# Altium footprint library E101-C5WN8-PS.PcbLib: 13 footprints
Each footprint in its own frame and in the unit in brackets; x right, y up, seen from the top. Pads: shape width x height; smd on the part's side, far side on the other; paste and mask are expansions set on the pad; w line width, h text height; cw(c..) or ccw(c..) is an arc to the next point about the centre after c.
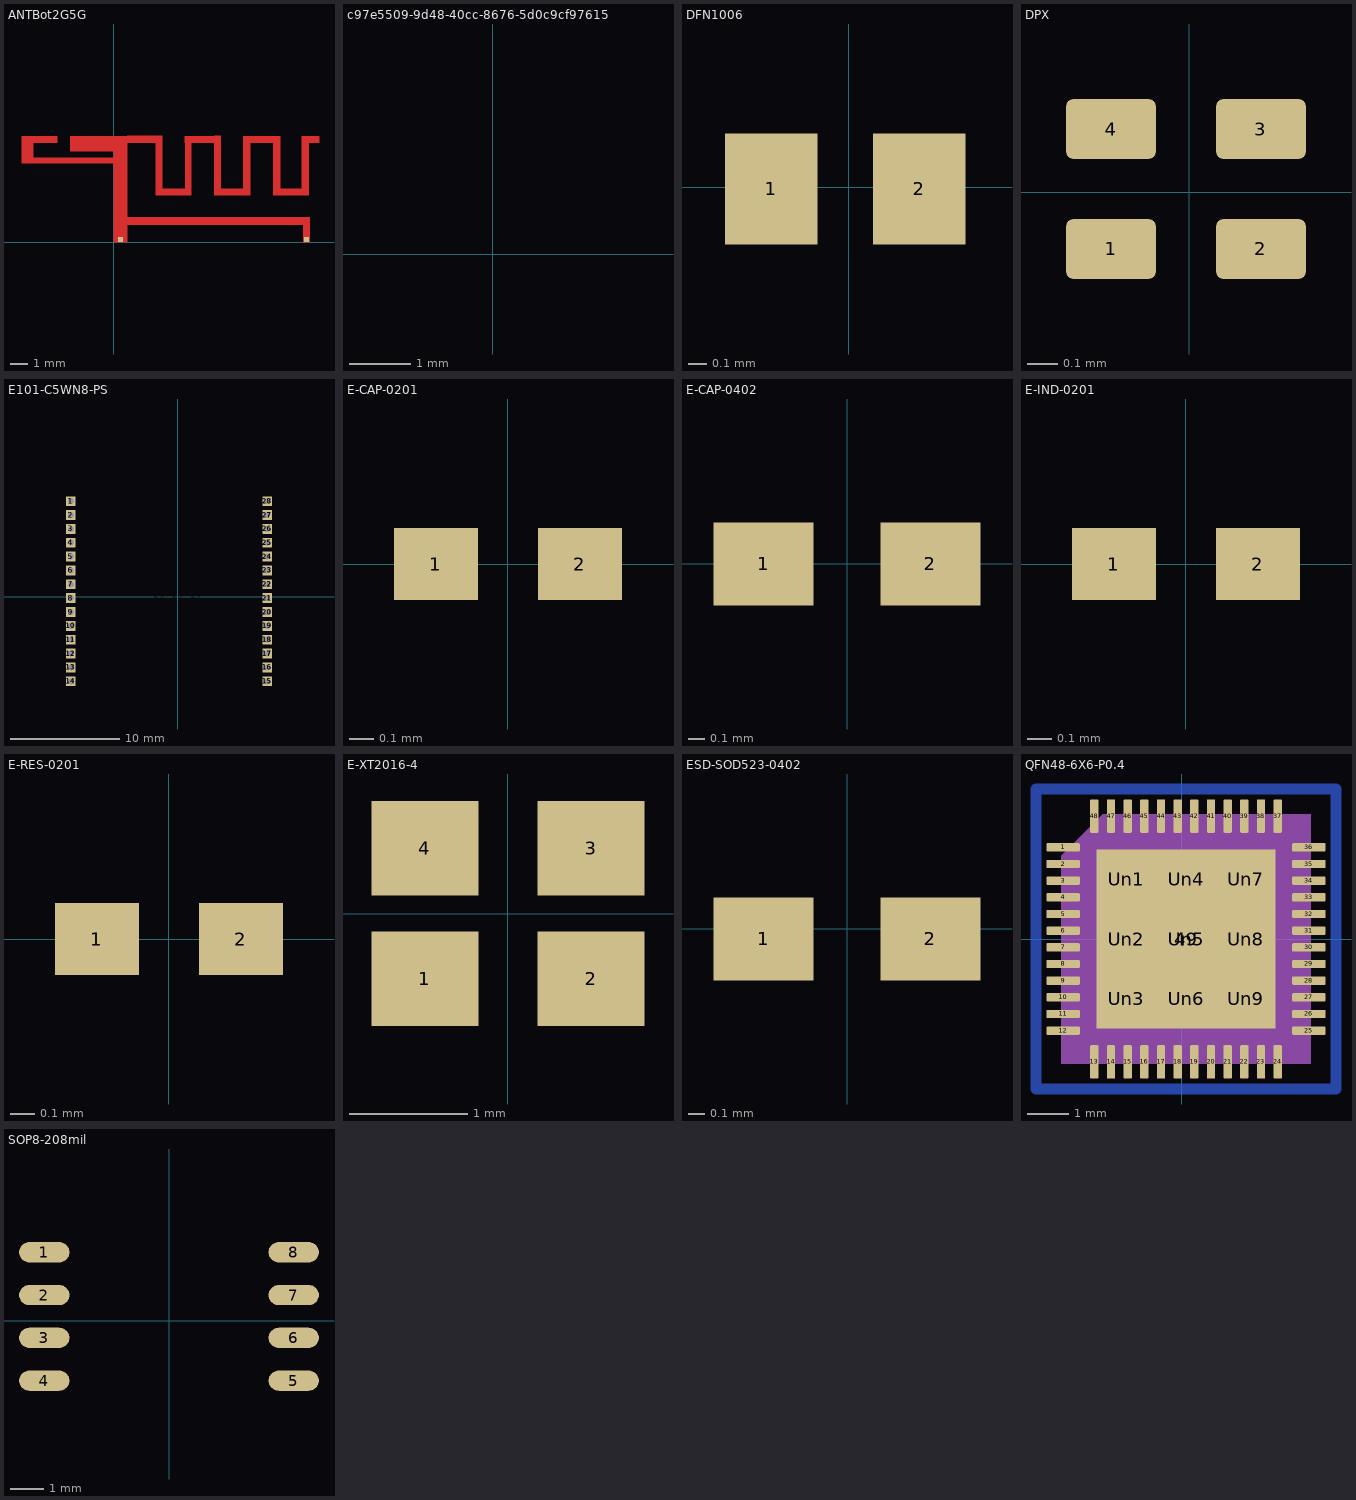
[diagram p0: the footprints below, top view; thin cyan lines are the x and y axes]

## ANTBot2G5G [mm]
pads (2):
  rect 0.3x0.3 smd paste-0.3 mask-0.3: 1(0.379,0.15) 2(11.046,0.15)
Top Layer:
  region: 4.43,3.06 4.43,2.683 4.427,2.68 2.78,2.68 2.78,3.07 4.42,3.07
  region: 11.239,0 10.855,0 10.855,0.987 0.765,0.987 0.765,1.43 11.239,1.43
  region: 6.14,5.7 4.07,5.7 4.07,6.08 4.08,6.09 6.14,6.09
  region: 2.783,2.683 2.78,2.68 2.39,2.68 2.39,5.7 2.783,5.7
  region: 4.43,3.06 4.42,3.05 4.08,3.05 4.08,6.09 4.43,6.09
  region: 7.43,2.68 6.14,2.68 6.13,2.69 6.13,3.07 7.43,3.07
  region: 6.14,6.09 6.14,2.68 5.75,2.68 5.75,6.1 6.13,6.1
  region: 2.783,5.7 0.765,5.7 0.765,6.093 2.783,6.093
  region: 11.77,5.7 11.18,5.7 11.18,6.09 11.77,6.09
  region: 9.54,5.7 7.43,5.7 7.43,6.09 9.54,6.09
  region: 0,5.22 -2.52,5.22 -2.52,6.09 0,6.09
  region: -3.25,5.7 -4.63,5.7 -4.63,6.09 -3.25,6.09
  region: 0,4.52 -5.29,4.52 -5.29,4.83 0,4.83
  region: -4.63,4.83 -5.29,4.83 -5.29,6.09 -4.63,6.09
  region: 10.79,2.68 9.54,2.68 9.54,3.07 10.79,3.07
  region: 11.18,2.68 10.79,2.68 10.79,6.09 11.18,6.09
  region: 9.54,2.68 9.14,2.68 9.14,6.09 9.54,6.09
  region: 7.83,2.68 7.43,2.68 7.43,6.09 7.83,6.09
  region: 0.77,0 0,0 0,6.09 0.77,6.09
Mid-Layer 2:
  region: -5.44,4.81 -4.7,4.81 -4.7,4.8 -5.44,4.8 -5.45,4.81 -5.45,4.82
  region: -1.91,5.22 -5.45,5.22 -5.45,6.09 -1.91,6.09
  region: 0.77,1.43 0,1.43 0,6.09 0.77,6.09

## c97e5509-9d48-40cc-8676-5d0c9cf97615 [mm]
Mid-Layer 7:
  lines w0.254: -2.019,-0.673 -2.007,-0.673 ; -2.007,-0.66 -1.981,-0.66 ; -2.007,-0.648 -1.956,-0.648 ; -1.981,-0.622 -1.918,-0.622 -1.803,-0.559 ; -0.381,0.305 -1.435,0.318 ; 0.025,-0.419 -0.838,-0.394 ; 0.089,-0.178 0.178,-0.178 ; 0.114,-0.191 0.191,-0.191 ; 0.127,-0.203 0.203,-0.203 ; 0.165,-0.165 -0.368,-0.114 ; 0.165,1.486 1.181,1.499 -0.064,1.511 1.168,1.524 -0.165,1.537 1.156,1.549 -0.241,1.562 1.143,1.575 -0.343,1.6 ; 0.33,1.473 1.207,1.473 0.47,1.46 1.219,1.448 0.635,1.435 1.232,1.422 0.737,1.41 1.245,1.397 0.8,1.384 1.257,1.372 0.864,1.359 1.27,1.283 0.978,1.27 1.207,1.257 1.029,1.206 1.118,1.206 ; 0.368,-0.508 0.445,-0.508 ; 0.368,-0.495 0.445,-0.495 ; 0.381,-0.533 0.457,-0.533 ; 0.381,-0.521 0.445,-0.521 ; 0.394,-0.559 0.457,-0.559 ; 0.394,-0.546 0.457,-0.546 ; 0.406,-0.584 0.47,-0.584 ; 0.419,-0.635 0.508,-0.635 ; 0.419,-0.622 0.495,-0.622 0.406,-0.61 0.483,-0.61 ; 0.495,0.191 0.597,0.216 ; 0.61,-0.406 0.711,-0.406 ; 0.61,0.064 0.699,0.064 0.864,0 ; 0.61,0.076 0.699,0.076 ; 0.635,-0.419 0.724,-0.419 ; 0.635,0.178 0.711,0.178 ; 0.635,0.368 0.724,0.368 ; 0.66,0.191 0.711,0.191 ; 0.66,0.203 0.724,0.203 ; 0.673,0.356 0.737,0.356 ; 0.775,0.343 0.851,0.343 0.749,0.229 0.673,0.229 0.864,0.267 0.737,0.216 0.673,0.216 0.876,0.241 ; 0.775,0.419 0.864,0.419 0.66,0.508 ; 0.787,0.064 0.876,0.064 ; 0.787,0.356 0.851,0.356 0.673,0.343 ; 0.787,0.368 0.851,0.368 0.673,0.343 ; 0.787,0.406 0.864,0.406 0.66,0.508 ; 0.8,0.076 0.876,0.076 ; 0.813,0.089 0.876,0.089 ; 0.813,0.102 0.876,0.102 ; 0.813,0.229 0.876,0.229 ; 0.813,0.597 0.826,0.597 ; 0.826,0.114 0.876,0.114 ; 0.826,0.127 0.876,0.127 ; 0.826,0.14 0.876,0.14 ; 0.826,0.152 0.876,0.152 ; 0.826,0.178 0.876,0.178 ; 0.826,0.191 0.876,0.191 ; 0.826,0.203 0.876,0.203 ; 0.826,0.216 0.876,0.216 ; 0.838,0.165 0.876,0.165 ; 0.889,-0.191 0.775,-0.178 0.876,-0.165 0.762,-0.152 0.864,-0.14 0.749,-0.127 0.864,-0.114 0.737,-0.102 0.864,-0.089 0.724,-0.076 0.864,-0.064 0.699,-0.038 0.864,0 ; 0.889,0.419 0.953,0.419 ; 0.902,0.406 0.965,0.406 ; 0.914,0.394 0.978,0.394 ; 0.927,0.381 0.991,0.381 ; 0.94,0.356 1.016,0.356 ; 0.94,0.368 1.003,0.368 ; 0.953,-0.178 1.041,-0.178 ; 0.953,0.318 1.029,0.318 ; 0.953,0.33 1.029,0.33 ; 0.953,0.343 1.016,0.343 ; 0.965,-0.165 1.054,-0.165 ; 0.965,-0.152 1.054,-0.152 ; 0.965,0.254 1.041,0.254 ; 0.965,0.267 1.041,0.267 ; 0.965,0.279 1.041,0.279 ; 0.965,0.292 1.041,0.292 ; 0.965,0.305 1.029,0.305 ; 0.978,-0.14 1.067,-0.14 ; 0.978,-0.127 1.067,-0.127 ; 0.978,0.127 1.041,0.127 ; 0.978,0.14 1.041,0.14 ; 0.978,0.152 1.041,0.152 ; 0.978,0.165 1.041,0.165 ; 0.978,0.178 1.041,0.178 ; 0.978,0.191 1.041,0.191 ; 0.978,0.203 1.041,0.203 ; 0.978,0.216 1.041,0.216 ; 0.978,0.229 1.041,0.229 ; 0.978,0.241 1.041,0.241 ; 0.991,-0.114 1.067,-0.114 ; 0.991,-0.102 1.067,-0.102 ; 0.991,-0.089 1.08,-0.089 ; 0.991,-0.076 1.08,-0.076 ; 0.991,-0.064 1.08,-0.064 ; 0.991,-0.051 1.067,-0.051 ; 0.991,-0.038 1.067,-0.038 ; 0.991,-0.025 1.067,-0.025 ; 0.991,-0.013 1.067,-0.013 ; 0.991,0 1.067,0 ; 0.991,0.013 1.067,0.013 ; 0.991,0.025 1.054,0.025 ; 0.991,0.038 1.054,0.038 ; 0.991,0.051 1.054,0.051 ; 0.991,0.064 1.054,0.064 ; 0.991,0.076 1.054,0.076 ; 0.991,0.089 1.041,0.089 ; 0.991,0.102 1.041,0.102 ; 0.991,0.114 1.041,0.114 ; 1.156,-0.559 1.207,-0.559 ; 1.168,-0.546 1.207,-0.546 ; 1.168,-0.533 1.207,-0.533 ; 1.181,-0.521 1.207,-0.521 ; 1.181,-0.508 1.207,-0.508 ; 1.194,-0.495 1.207,-0.495 ; 1.194,-0.483 1.219,-0.483 ; 1.194,-0.47 1.219,-0.47 ; 1.207,-0.457 1.232,-0.457 ; 1.207,-0.445 1.232,-0.445 ; 1.219,-0.432 1.245,-0.432 2.362,-0.419 1.245,-0.419 1.219,-0.419 ; 1.232,-0.406 1.257,-0.406 2.337,-0.368 ; 1.232,-0.394 1.27,-0.394 2.337,-0.368 ; -1.943,-0.94 -2.184,-0.965 -1.943,-0.94 ; -1.943,-0.94 -2.159,-0.94 -1.943,-0.94 ; -1.892,-0.61 -1.803,-0.559 ; -1.892,-0.61 -1.981,-0.61 -1.892,-0.61 ; -1.892,-0.61 -1.803,-0.559 ; -1.803,-0.559 -1.93,-0.521 -1.714,-0.508 -1.905,-0.495 -1.676,-0.483 -1.892,-0.47 -1.638,-0.457 -1.88,-0.445 -1.587,-0.432 -1.867,-0.419 -1.549,-0.406 -1.854,-0.394 -1.499,-0.381 -1.829,-0.368 -1.46,-0.356 -1.816,-0.343 -1.422,-0.33 -1.803,-0.318 -1.372,-0.305 -1.791,-0.292 -1.333,-0.279 -1.778,-0.267 -1.295,-0.254 -1.753,-0.241 -1.245,-0.229 -1.74,-0.216 -1.206,-0.203 -1.727,-0.191 -1.168,-0.178 -1.714,-0.165 -1.13,-0.152 -1.702,-0.14 -1.079,-0.127 -1.689,-0.114 -1.041,-0.102 -1.664,-0.089 -1.003,-0.076 -1.651,-0.064 -0.965,-0.051 -1.638,-0.038 -0.914,-0.025 -1.626,-0.013 -0.876,0 -1.613,0.013 -0.838,0.025 -1.6,0.038 -0.787,0.051 -1.587,0.064 -0.749,0.076 -1.562,0.089 -0.711,0.102 -1.549,0.114 -0.673,0.127 -1.537,0.14 -0.622,0.152 -1.524,0.165 -0.584,0.178 -1.511,0.191 -0.546,0.203 -1.499,0.216 -0.495,0.229 -1.473,0.241 -0.457,0.254 -1.46,0.267 -0.432,0.356 -1.397,0.368 -0.47,0.381 -1.384,0.394 -0.495,0.406 -1.372,0.419 -0.521,0.432 -1.359,0.445 -0.559,0.457 -1.346,0.47 -0.584,0.483 -1.333,0.495 -0.61,0.508 -1.308,0.521 -0.635,0.533 -1.295,0.546 -0.66,0.559 -1.283,0.572 -0.686,0.584 -1.27,0.597 -0.711,0.61 -1.257,0.622 -0.737,0.635 -1.232,0.648 -0.762,0.66 -1.219,0.673 -0.775,0.686 -1.206,0.699 -0.8,0.711 -1.194,0.724 -0.813,0.737 -1.168,0.749 -0.826,0.762 -1.156,0.775 -0.838,0.787 -1.143,0.8 -0.864,0.813 -1.13,0.826 -0.876,0.838 -1.118,0.851 -0.889,0.864 -1.029,0.927 ; -1.714,-0.927 2.68,-0.953 -1.714,-0.927 ; -1.714,-0.927 2.654,-0.902 ; -1.714,-0.927 2.654,-0.902 ; -1.638,-0.876 2.654,-0.902 ; -1.638,-0.876 2.629,-0.851 ; -1.638,-0.876 2.629,-0.851 ; -1.638,-0.876 2.654,-0.902 ; -1.549,-0.826 2.629,-0.851 ; -1.549,-0.826 2.591,-0.8 ; -1.549,-0.826 2.591,-0.8 ; -1.549,-0.826 2.629,-0.851 ; -1.46,-0.775 2.591,-0.8 ; -1.46,-0.775 2.565,-0.749 ; -1.46,-0.775 2.565,-0.749 ; -1.46,-0.775 2.591,-0.8 ; -1.435,0.318 -0.406,0.33 ; -1.435,0.318 -0.406,0.33 ; -1.384,-0.724 2.565,-0.749 ; -1.384,-0.724 2.527,-0.699 ; -1.384,-0.724 2.527,-0.699 ; -1.384,-0.724 2.565,-0.749 ; -1.029,0.927 -1.067,0.927 -1.029,0.927 ; -0.838,-0.394 0.216,-0.432 -0.914,-0.445 0.216,-0.457 -0.965,-0.47 0.216,-0.483 -1.003,-0.495 0.216,-0.508 -1.041,-0.521 0.216,-0.533 -1.092,-0.546 0.216,-0.559 -1.13,-0.572 0.216,-0.584 -1.168,-0.597 0.216,-0.61 -1.219,-0.622 0.229,-0.635 -1.257,-0.648 0.241,-0.66 -1.295,-0.673 2.515,-0.673 1.054,-0.673 0.711,-0.66 1.041,-0.648 0.711,-0.635 1.016,-0.622 0.711,-0.61 1.003,-0.597 0.724,-0.584 0.991,-0.572 0.711,-0.559 0.991,-0.546 0.686,-0.47 0.762,-0.47 0.965,-0.394 0.813,-0.318 0.978,-0.33 0.826,-0.343 0.978,-0.356 0.826,-0.368 0.978,-0.381 0.749,-0.457 0.673,-0.457 0.991,-0.521 0.686,-0.483 0.775,-0.483 0.978,-0.419 0.737,-0.445 0.66,-0.445 0.978,-0.495 0.826,-0.47 ; -0.838,-0.394 -0.025,-0.368 ; -0.838,-0.394 -0.025,-0.368 ; -0.749,-0.343 -0.025,-0.368 ; -0.749,-0.343 -0.025,-0.318 ; -0.749,-0.343 -0.025,-0.318 ; -0.749,-0.343 -0.025,-0.368 ; -0.66,-0.292 -0.025,-0.318 ; -0.66,-0.292 -0.025,-0.267 ; -0.66,-0.292 -0.025,-0.267 ; -0.66,-0.292 -0.025,-0.318 ; -0.597,1.753 1.041,1.727 ; -0.597,1.753 1.016,1.778 ; -0.597,1.753 1.016,1.778 ; -0.597,1.753 1.041,1.727 ; -0.584,-0.241 -0.025,-0.267 ; -0.584,-0.241 -0.025,-0.216 ; -0.584,-0.241 -0.025,-0.216 ; -0.584,-0.241 -0.025,-0.267 ; -0.559,1.702 1.08,1.676 ; -0.559,1.702 1.041,1.727 ; -0.559,1.702 1.041,1.727 ; -0.559,1.702 1.08,1.676 ; -0.559,1.803 1.016,1.778 ; -0.559,1.803 0.978,1.829 ; -0.559,1.803 0.978,1.829 ; -0.559,1.803 1.016,1.778 ; -0.533,1.854 0.978,1.829 ; -0.533,1.854 0.953,1.88 ; -0.533,1.854 0.953,1.88 ; -0.533,1.854 0.978,1.829 ; -0.508,1.905 0.953,1.88 ; -0.508,1.905 0.914,1.93 ; -0.508,1.905 0.914,1.93 ; -0.508,1.905 0.953,1.88 ; -0.47,1.956 0.914,1.93 ; -0.47,1.956 0.889,1.981 ; -0.47,1.956 0.889,1.981 ; -0.47,1.956 0.914,1.93 ; -0.457,1.651 1.105,1.626 ; -0.457,1.651 1.08,1.676 ; -0.457,1.651 1.08,1.676 ; -0.457,1.651 1.105,1.626 ; -0.445,2.007 0.889,1.981 ; -0.445,2.007 0.864,2.032 ; -0.445,2.007 0.864,2.032 ; -0.445,2.007 0.889,1.981 ; -0.406,0.33 -1.422,0.33 -0.406,0.33 ; -0.406,2.057 0.864,2.032 ; -0.406,2.057 0.826,2.083 ; -0.406,2.057 0.826,2.083 ; -0.406,2.057 0.864,2.032 ; -0.381,2.108 0.826,2.083 ; -0.381,2.108 0.8,2.134 ; -0.381,2.108 0.8,2.134 ; -0.381,2.108 0.826,2.083 ; -0.368,-0.114 0.14,-0.14 -0.47,-0.178 -0.013,-0.203 ; -0.368,-0.114 0.089,-0.089 ; -0.368,-0.114 0.089,-0.089 ; -0.356,2.159 0.8,2.134 ; -0.356,2.159 0.762,2.184 ; -0.356,2.159 0.762,2.184 ; -0.356,2.159 0.8,2.134 ; -0.343,1.6 1.105,1.626 ; -0.343,1.6 1.105,1.626 ; -0.318,2.21 0.762,2.184 ; -0.318,2.21 0.737,2.235 ; -0.318,2.21 0.737,2.235 ; -0.318,2.21 0.762,2.184 ; -0.292,2.261 0.737,2.235 ; -0.292,2.261 0.699,2.286 ; -0.292,2.261 0.699,2.286 ; -0.292,2.261 0.737,2.235 ; -0.279,-0.064 0.089,-0.089 ; -0.279,-0.064 0.038,-0.038 ; -0.279,-0.064 0.038,-0.038 ; -0.279,-0.064 0.089,-0.089 ; -0.267,2.311 0.699,2.286 ; -0.267,2.311 0.673,2.337 ; -0.267,2.311 0.673,2.337 ; -0.267,2.311 0.699,2.286 ; -0.229,2.362 0.673,2.337 ; -0.229,2.362 0.635,2.388 ; -0.229,2.362 0.635,2.388 ; -0.229,2.362 0.673,2.337 ; -0.203,2.413 0.635,2.388 ; -0.203,2.413 0.61,2.438 ; -0.203,2.413 0.61,2.438 ; -0.203,2.413 0.635,2.388 ; -0.191,-0.013 0.038,-0.038 ; -0.191,-0.013 -0.038,0.038 ; -0.191,-0.013 -0.038,0.038 ; -0.191,-0.013 0.038,-0.038 ; -0.178,2.464 0.61,2.438 ; -0.178,2.464 0.572,2.489 ; -0.178,2.464 0.572,2.489 ; -0.178,2.464 0.61,2.438 ; -0.14,2.515 0.572,2.489 ; -0.14,2.515 0.546,2.54 ; -0.14,2.515 0.546,2.54 ; -0.14,2.515 0.572,2.489 ; -0.114,2.565 0.546,2.54 ; -0.114,2.565 0.508,2.591 ; -0.114,2.565 0.508,2.591 ; -0.114,2.565 0.546,2.54 ; -0.089,2.616 0.508,2.591 ; -0.089,2.616 0.483,2.642 ; -0.089,2.616 0.483,2.642 ; -0.089,2.616 0.508,2.591 ; -0.051,2.667 0.483,2.642 ; -0.051,2.667 0.445,2.692 ; -0.051,2.667 0.445,2.692 ; -0.051,2.667 0.483,2.642 ; -0.038,0.038 -0.102,0.038 -0.038,0.038 ; -0.025,-0.216 -0.533,-0.216 -0.025,-0.216 ; -0.025,2.718 0.445,2.692 ; -0.025,2.718 0.419,2.743 ; -0.025,2.718 0.419,2.743 ; -0.025,2.718 0.445,2.692 ; -0.013,-0.203 -0.508,-0.203 -0.013,-0.203 ; 0,2.769 0.419,2.743 ; 0,2.769 0.394,2.794 ; 0,2.769 0.394,2.794 ; 0,2.769 0.419,2.743 ; 0.038,2.819 0.394,2.794 ; 0.038,2.819 0.356,2.845 ; 0.038,2.819 0.356,2.845 ; 0.038,2.819 0.394,2.794 ; 0.064,2.87 0.356,2.845 ; 0.064,2.87 0.33,2.896 ; 0.064,2.87 0.33,2.896 ; 0.064,2.87 0.356,2.845 ; 0.089,2.921 0.33,2.896 ; 0.089,2.921 0.292,2.946 ; 0.089,2.921 0.292,2.946 ; 0.089,2.921 0.33,2.896 ; 0.178,-0.368 0.445,-0.445 ; 0.178,-0.368 0.445,-0.445 ; 0.178,-0.368 0.343,-0.343 ; 0.178,-0.368 0.343,-0.343 ; 0.292,2.946 0.114,2.946 0.292,2.946 ; 0.343,-0.343 0.229,-0.419 0.127,-0.419 0.343,-0.343 ; 0.419,0.292 0.597,0.267 ; 0.419,0.292 0.597,0.318 ; 0.419,0.292 0.597,0.318 ; 0.419,0.292 0.597,0.267 ; 0.432,0.368 0.597,0.318 ; 0.432,0.368 0.584,0.356 ; 0.432,0.368 0.584,0.356 ; 0.432,0.368 0.597,0.318 ; 0.445,-0.47 0.673,-0.356 ; 0.445,-0.47 0.673,-0.356 ; 0.445,-0.47 0.356,-0.47 0.445,-0.47 ; 0.445,-0.445 0.33,-0.445 0.445,-0.445 ; 0.457,0.241 0.597,0.216 ; 0.457,0.241 0.597,0.267 ; 0.457,0.241 0.597,0.267 ; 0.457,0.241 0.597,0.216 ; 0.47,-0.33 0.673,-0.356 ; 0.47,-0.33 0.572,-0.305 ; 0.47,-0.33 0.572,-0.305 ; 0.47,-0.33 0.673,-0.356 ; 0.495,0.406 0.724,0.381 0.495,0.406 ; 0.495,0.406 0.724,0.432 ; 0.495,0.406 0.724,0.432 ; 0.572,-0.305 0.546,-0.305 0.572,-0.305 ; 0.584,0.102 0.699,0.152 0.584,0.102 ; 0.584,0.102 0.686,0.127 ; 0.584,0.102 0.686,0.127 ; 0.584,0.356 0.419,0.356 0.584,0.356 ; 0.597,0.178 0.686,0.127 ; 0.597,0.178 0.508,0.178 0.597,0.178 ; 0.597,0.178 0.686,0.127 ; 0.66,0.508 0.838,0.559 ; 0.66,0.508 0.838,0.559 ; 0.673,0.343 0.787,0.381 0.851,0.381 0.737,0.343 0.673,0.343 ; 0.711,-0.051 0.864,0 ; 0.711,-0.051 0.787,0.051 0.864,0.051 0.622,0.051 0.711,0.051 0.851,-0.051 0.711,-0.051 ; 0.711,-0.051 0.864,0 ; 0.724,0.432 0.533,0.432 0.724,0.432 ; 0.8,-0.241 1.029,-0.216 0.8,-0.241 ; 0.8,-0.241 1.003,-0.267 ; 0.8,-0.241 1.003,-0.267 ; 0.813,-0.305 1.003,-0.267 ; 0.813,-0.305 0.991,-0.279 ; 0.813,-0.305 0.991,-0.279 ; 0.813,-0.305 1.003,-0.267 ; 0.826,-0.47 0.978,-0.445 ; 0.826,-0.47 0.978,-0.445 ; 0.838,0.559 0.749,0.559 0.838,0.559 ; 0.978,-0.445 0.826,-0.445 0.978,-0.445 ; 0.991,-0.279 0.813,-0.279 0.991,-0.279 ; 1.08,1.181 1.105,1.194 ; 1.08,1.181 1.041,1.181 1.08,1.181 ; 1.105,1.194 1.029,1.194 1.105,1.194 ; 1.245,-0.381 2.337,-0.368 ; 1.245,-0.381 2.299,-0.318 ; 1.245,-0.381 1.283,-0.381 2.299,-0.318 ; 1.245,-0.381 2.337,-0.368 ; 1.27,0.826 1.626,0.8 ; 1.27,0.826 1.6,0.851 ; 1.27,0.826 1.6,0.851 ; 1.27,0.826 1.626,0.8 ; 1.27,0.876 1.6,0.851 ; 1.27,0.876 1.562,0.902 ; 1.27,0.876 1.562,0.902 ; 1.27,0.876 1.6,0.851 ; 1.283,1.333 0.953,1.295 1.283,1.333 ; 1.283,1.333 0.902,1.333 1.283,1.333 ; 1.308,0.775 1.651,0.749 ; 1.308,0.775 1.626,0.8 ; 1.308,0.775 1.626,0.8 ; 1.308,0.775 1.651,0.749 ; 1.321,-0.521 2.438,-0.546 ; 1.321,-0.521 2.413,-0.495 ; 1.321,-0.521 2.413,-0.495 ; 1.321,-0.521 2.438,-0.546 ; 1.334,-0.47 2.413,-0.495 ; 1.334,-0.47 2.375,-0.445 ; 1.334,-0.47 2.375,-0.445 ; 1.334,-0.47 2.413,-0.495 ; 1.334,0.724 1.689,0.699 ; 1.334,0.724 1.651,0.749 ; 1.334,0.724 1.651,0.749 ; 1.334,0.724 1.689,0.699 ; 1.359,0.927 1.562,0.902 ; 1.359,0.927 1.524,0.978 ; 1.359,0.927 1.524,0.978 ; 1.359,0.927 1.562,0.902 ; 1.372,0.673 1.715,0.648 ; 1.372,0.673 1.689,0.699 ; 1.372,0.673 1.689,0.699 ; 1.372,0.673 1.715,0.648 ; 1.41,-0.241 2.273,-0.267 ; 1.41,-0.241 2.235,-0.216 ; 1.41,-0.241 2.235,-0.216 ; 1.41,-0.241 2.273,-0.267 ; 1.41,0.622 1.753,0.597 ; 1.41,0.622 1.715,0.648 ; 1.41,0.622 1.715,0.648 ; 1.41,0.622 1.753,0.597 ; 1.422,-0.191 2.235,-0.216 ; 1.422,-0.191 2.21,-0.165 ; 1.422,-0.191 2.21,-0.165 ; 1.422,-0.191 2.235,-0.216 ; 1.435,-0.14 2.21,-0.165 ; 1.435,-0.14 2.184,-0.114 ; 1.435,-0.14 2.184,-0.114 ; 1.435,-0.14 2.21,-0.165 ; 1.435,0.572 1.778,0.546 ; 1.435,0.572 1.753,0.597 ; 1.435,0.572 1.753,0.597 ; 1.435,0.572 1.778,0.546 ; 1.448,-0.089 2.184,-0.114 ; 1.448,-0.089 2.146,-0.064 ; 1.448,-0.089 2.146,-0.064 ; 1.448,-0.089 2.184,-0.114 ; 1.461,-0.038 2.146,-0.064 ; 1.461,-0.038 2.121,-0.013 ; 1.461,-0.038 2.121,-0.013 ; 1.461,-0.038 2.146,-0.064 ; 1.473,0.013 2.121,-0.013 ; 1.473,0.013 2.083,0.038 ; 1.473,0.013 2.083,0.038 ; 1.473,0.013 2.121,-0.013 ; 1.473,0.521 1.816,0.495 ; 1.473,0.521 1.778,0.546 ; 1.473,0.521 1.778,0.546 ; 1.473,0.521 1.816,0.495 ; 1.486,0.064 2.083,0.038 ; 1.486,0.064 2.057,0.089 ; 1.486,0.064 2.057,0.089 ; 1.486,0.064 2.083,0.038 ; 1.499,0.114 2.057,0.089 ; 1.499,0.114 2.019,0.14 ; 1.499,0.114 2.019,0.14 ; 1.499,0.114 2.057,0.089 ; 1.499,0.47 1.842,0.445 ; 1.499,0.47 1.816,0.495 ; 1.499,0.47 1.816,0.495 ; 1.499,0.47 1.842,0.445 ; 1.511,0.165 2.019,0.14 ; 1.511,0.165 1.994,0.191 ; 1.511,0.165 1.994,0.191 ; 1.511,0.165 2.019,0.14 ; 1.524,0.216 1.994,0.191 ; 1.524,0.216 1.969,0.241 ; 1.524,0.216 1.969,0.241 ; 1.524,0.216 1.994,0.191 ; 1.524,0.419 1.867,0.394 ; 1.524,0.419 1.842,0.445 ; 1.524,0.419 1.842,0.445 ; 1.524,0.419 1.867,0.394 ; 1.524,0.978 1.448,0.978 1.524,0.978 ; 1.537,0.267 1.969,0.241 ; 1.537,0.267 1.93,0.292 ; 1.537,0.267 1.93,0.292 ; 1.537,0.267 1.969,0.241 ; 1.537,0.318 1.93,0.292 ; 1.537,0.318 1.905,0.343 ; 1.537,0.318 1.905,0.343 ; 1.537,0.318 1.93,0.292 ; 1.537,0.368 1.905,0.343 ; 1.537,0.368 1.867,0.394 ; 1.537,0.368 1.867,0.394 ; 1.537,0.368 1.905,0.343 ; 2.273,-0.267 1.397,-0.292 2.273,-0.267 ; 2.299,-0.318 1.245,-0.368 1.308,-0.368 2.299,-0.318 ; 2.375,-0.445 1.334,-0.445 2.375,-0.445 ; 2.438,-0.546 1.219,-0.597 1.13,-0.597 2.489,-0.622 ; 2.438,-0.546 1.219,-0.61 1.13,-0.61 2.489,-0.622 ; 2.489,-0.622 1.143,-0.584 1.207,-0.584 2.464,-0.597 1.207,-0.572 1.156,-0.572 2.489,-0.622 ; 2.527,-0.699 -1.346,-0.699 2.527,-0.699 ; -2.108,-0.851 -2.019,-0.851 -2.108,-0.851 ; -2.095,-0.838 -2.032,-0.838 -2.095,-0.838 ; -2.083,-0.826 -2.045,-0.826 -2.083,-0.826 ; -2.083,-0.813 -2.045,-0.813 -2.083,-0.813 ; -2.07,-0.8 -2.057,-0.8 -2.07,-0.8 ; -1.994,-0.635 -1.93,-0.635 -1.994,-0.635 ; -1.067,0.914 -1.003,0.914 -1.067,0.914 ; -0.076,0.051 -0.051,0.051 -0.076,0.051 ; 0.14,-0.216 0.216,-0.216 0.14,-0.216 ; 0.152,-0.229 0.229,-0.229 0.152,-0.229 ; 0.165,-0.254 0.254,-0.254 0.165,-0.254 ; 0.165,-0.241 0.241,-0.241 0.165,-0.241 ; 0.165,3.035 0.241,3.035 0.165,3.035 ; 0.165,3.048 0.229,3.048 0.165,3.048 ; 0.178,-0.267 0.267,-0.267 0.178,-0.267 ; 0.178,3.061 0.229,3.061 0.178,3.061 ; 0.178,3.073 0.216,3.073 0.178,3.073 ; 0.191,3.086 0.203,3.086 0.191,3.086 ; 0.356,-0.483 0.445,-0.483 0.356,-0.483 ; 0.394,-0.572 0.457,-0.572 0.394,-0.572 ; 0.406,-0.597 0.483,-0.597 0.406,-0.597 ; 0.584,0.457 0.864,0.394 0.787,0.394 0.927,0.445 0.584,0.457 ; 0.648,-0.432 0.724,-0.432 0.648,-0.432 ; 0.775,0.572 0.826,0.572 0.775,0.572 ; 0.8,0.584 0.826,0.584 0.8,0.584 ; 1.461,0.991 1.511,0.991 1.461,0.991 ; 1.486,1.003 1.499,1.003 1.486,1.003

## DFN1006 [mm]
pads (2):
  rect 0.5x0.6 smd paste-0.6 mask-0.6: 1(-0.42,-0.01) 2(0.38,-0.01)
Mid-Layer 5:
  lines w0.254: -0.82,-0.41 -0.82,0.39 ; 0.286,-0.41 0.8,-0.41 0.8,0.39 0.286,0.39

## DPX [mm]
pads (4):
  rrect25% 0.3x0.2 smd paste-0.3 mask-0.3: 1(-0.26,-0.19) 2(0.24,-0.19) 3(0.24,0.21) 4(-0.26,0.21)
Mid-Layer 5:
  lines w0.254: -0.51,-0.09 -0.414,-0.186 0.49,-0.19 0.49,0.21 -0.51,0.21 -0.51,-0.09

## E101-C5WN8-PS [mm]
pads (65):
  rect 0.9x0.9 hole 0.55 paste-2539.97 mask-0.9: 1(-9.82,8.75) 2(-9.82,7.48) 3(-9.82,6.21) 4(-9.82,4.94) 5(-9.82,3.67) 6(-9.82,2.4) 7(-9.82,1.13) 8(-9.82,-0.14) 9(-9.82,-1.41) 10(-9.82,-2.68) 11(-9.82,-3.95) 12(-9.82,-5.22) 13(-9.82,-6.49) 14(-9.82,-7.76) 15(8.18,-7.76) 16(8.18,-6.49) 17(8.18,-5.22) 18(8.18,-3.95) 19(8.18,-2.68) 20(8.18,-1.41) 21(8.18,-0.14) 22(8.18,1.13) 23(8.18,2.4) 24(8.18,3.67) 25(8.18,4.94) 26(8.18,6.21) 27(8.18,7.48) 28(8.18,8.75)
  rect 1.6x0.9 on Mid2 paste-1.6 mask-1.6: 1(-9.82,8.75) 2(-9.82,7.48) 3(-9.82,6.21) 4(-9.82,4.94) 5(-9.82,3.67) 6(-9.82,2.4) 7(-9.82,1.13) 8(-9.82,-0.14) 9(-9.82,-1.41) 10(-9.82,-2.68) 11(-9.82,-3.95) 12(-9.82,-5.22) 13(-9.82,-6.49) 14(-9.82,-7.76) 15(8.18,-7.76) 16(8.18,-6.49) 17(8.18,-5.22) 18(8.18,-3.95) 19(8.18,-2.68) 20(8.18,-1.41) 21(8.18,-0.14) 22(8.18,1.13) 23(8.18,2.4) 24(8.18,3.67) 25(8.18,4.94) 26(8.18,6.21) 27(8.18,7.48) 28(8.18,8.75)
  rect 1.3x1.3 on Mid2 paste-1.3 mask-1.3: 29(-1.69,-1.54) 29(-1.69,0.16) 29(-1.69,1.86) 29(0.01,-1.54) 29(0.01,0.16) 29(0.01,1.86) 29(1.71,-1.54) 29(1.71,0.16) 29(1.71,1.86)
Mid-Layer 17:
  lines w0.254: 7.18,5.758 7.196,5.758
Mid-Layer 25:
  lines w0.254: -9.82,-10.76 -9.82,16.74 8.18,16.74 8.18,-10.76 -9.82,-10.76

## E-CAP-0201 [mm]
pads (2):
  rect 0.35x0.3 smd paste-0.35 mask-0.35: 1(-0.3,0) 2(0.3,0)
Mid-Layer 5:
  lines w0.254: -0.1,-0.3 -0.625,-0.3 -0.625,0 -0.625,0.3 -0.1,0.3 ; 0.1,-0.3 0.625,-0.3 0.625,0.3 0.1,0.3

## E-CAP-0402 [mm]
pads (2):
  rect 0.6x0.5 smd paste-0.6 mask-0.6: 1(-0.5,0) 2(0.5,0)
Mid-Layer 5:
  lines w0.254: -0.194,-0.4 -0.9,-0.4 -0.9,0.4 -0.194,0.4 ; 0.206,-0.4 0.9,-0.4 0.9,0.4 0.206,0.4

## E-IND-0201 [mm]
pads (2):
  rect 0.35x0.3 smd paste-0.35 mask-0.35: 1(-0.3,0) 2(0.3,0)
Mid-Layer 5:
  lines w0.254: -0.1,-0.3 -0.625,-0.3 -0.625,0 -0.625,0.3 -0.1,0.3 ; 0.1,-0.3 0.625,-0.3 0.625,0.3 0.1,0.3

## E-RES-0201 [mm]
pads (2):
  rect 0.35x0.3 smd paste-0.35 mask-0.35: 1(-0.3,0) 2(0.3,0)
Mid-Layer 5:
  lines w0.254: -0.1,-0.3 -0.625,-0.3 -0.625,0 -0.625,0.3 -0.1,0.3 ; 0.1,-0.3 0.625,-0.3 0.625,0.3 0.1,0.3

## E-XT2016-4 [mm]
pads (4):
  rect 0.9x0.8 smd paste-0.9 mask-0.9: 1(-0.7,-0.55) 2(0.7,-0.55) 3(0.7,0.55) 4(-0.7,0.55)
Mid-Layer 5:
  circle w0.254: c-0.71,-1.38 r0.1
  lines w0.254: -1.25,-1.05 1.25,-1.05 1.25,1.05 -1.25,1.05 -1.25,-1.05

## ESD-SOD523-0402 [mm]
pads (2):
  rect 0.6x0.5 smd paste-0.6 mask-0.6: 1(-0.5,-0.06) 2(0.5,-0.06)
Mid-Layer 5:
  lines w0.254: -0.194,-0.46 -0.9,-0.46 -0.9,0.34 -0.194,0.34 ; 0.206,-0.46 0.9,-0.46 0.9,0.34 0.206,0.34

## QFN48-6X6-P0.4 [mm]
pads (58):
  rrect25% 0.8x0.2 smd paste-0.8 mask-0.8: 1(-2.85,2.2) 2(-2.85,1.8) 3(-2.85,1.4) 4(-2.85,1) 5(-2.85,0.6) 6(-2.85,0.2) 7(-2.85,-0.2) 8(-2.85,-0.6) 9(-2.85,-1) 10(-2.85,-1.4) 11(-2.85,-1.8) 12(-2.85,-2.2) 25(3.05,-2.2) 26(3.05,-1.8) 27(3.05,-1.4) 28(3.05,-1) 29(3.05,-0.6) 30(3.05,-0.2) 31(3.05,0.2) 32(3.05,0.6) 33(3.05,1) 34(3.05,1.4) 35(3.05,1.8) 36(3.05,2.2)
  rrect25% 0.2x0.8 smd paste-0.8 mask-0.8: 13(-2.1,-2.95) 14(-1.7,-2.95) 15(-1.3,-2.95) 16(-0.9,-2.95) 17(-0.5,-2.95) 18(-0.1,-2.95) 19(0.3,-2.95) 20(0.7,-2.95) 21(1.1,-2.95) 22(1.5,-2.95) 23(1.9,-2.95) 24(2.3,-2.95) 37(2.3,2.95) 38(1.9,2.95) 39(1.5,2.95) 40(1.1,2.95) 41(0.7,2.95) 42(0.3,2.95) 43(-0.1,2.95) 44(-0.5,2.95) 45(-0.9,2.95) 46(-1.3,2.95) 47(-1.7,2.95) 48(-2.1,2.95)
  rect 4.3x4.3 smd paste-4.3 mask-4.3: 49(0.1,0)
  rrect22% 1.16x1.16 on Mid13 paste-1.16 mask-1.16: Un1(-1.33,1.43) Un2(-1.33,0) Un3(-1.33,-1.43) Un4(0.1,1.43) Un5(0.1,0) Un6(0.1,-1.43) Un7(1.53,1.43) Un8(1.53,0) Un9(1.53,-1.43)
Mid-Layer 5:
  region: -3.01,3.11 -3.25,3.44 -2.77,3.44
  lines w0.254: -3.01,-2.56 -3.01,-3.11 -2.46,-3.11 ; -3.01,2.56 -3.01,2.87 ; -2.71,3.11 -2.46,3.11 ; 2.66,-3.11 3.21,-3.11 3.21,-2.56 ; 2.66,3.11 3.21,3.11 3.21,2.56
Bottom Layer:
  lines w0.254: -3.5,-3.6 -3.5,3.6 3.7,3.6 3.7,-3.6 -3.5,-3.6
Mechanical 6:
  region: 3.1,-3 -2.9,-3 -2.9,2 -1.9,3 3.1,3

## SOP8-208mil [mm]
pads (8):
  rrect100% 1.5x0.6 smd paste-1.5 mask-1.5: 1(-3.7,2.03) 2(-3.7,0.76) 3(-3.7,-0.51) 4(-3.7,-1.78) 5(3.7,-1.78) 6(3.7,-0.51) 7(3.7,0.76) 8(3.7,2.03)
Mid-Layer 5:
  circle w0.254: c-4.1,2.775 r0.15
  circle w0.254: c-2.017,2.018 r0.15
  lines w0.254: -2.64,-2.49 2.64,-2.49 2.64,2.74 -2.64,2.74 -2.64,-2.49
